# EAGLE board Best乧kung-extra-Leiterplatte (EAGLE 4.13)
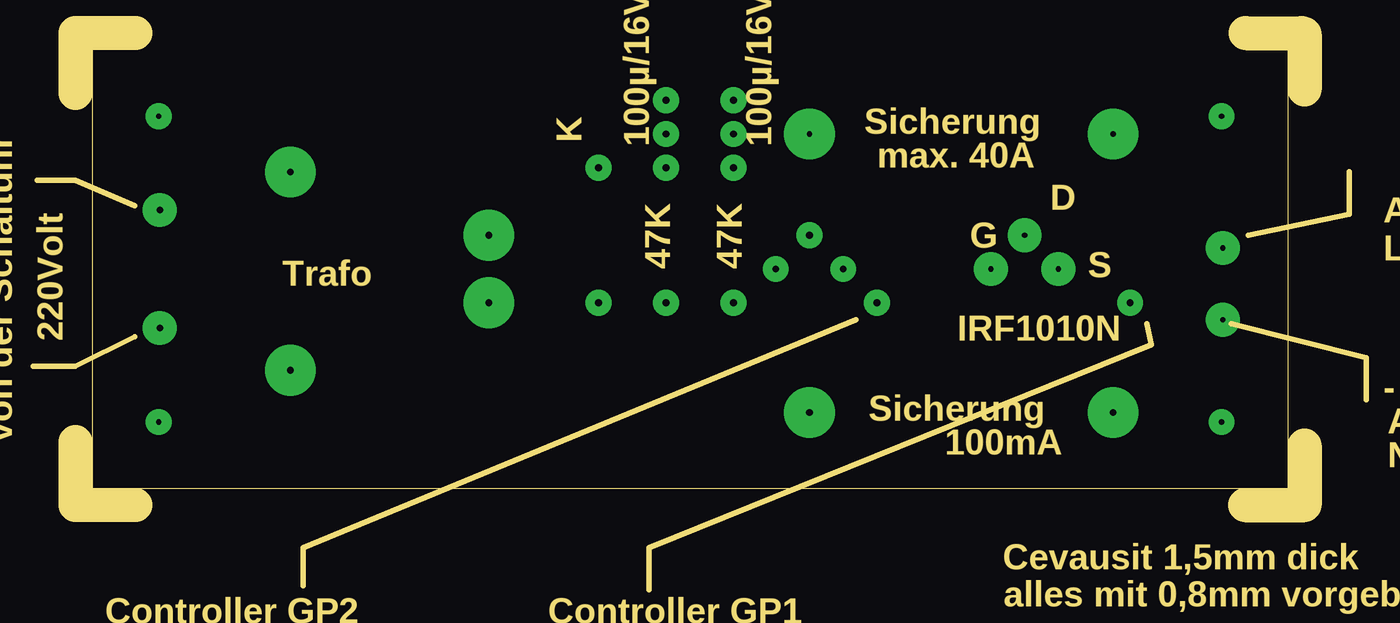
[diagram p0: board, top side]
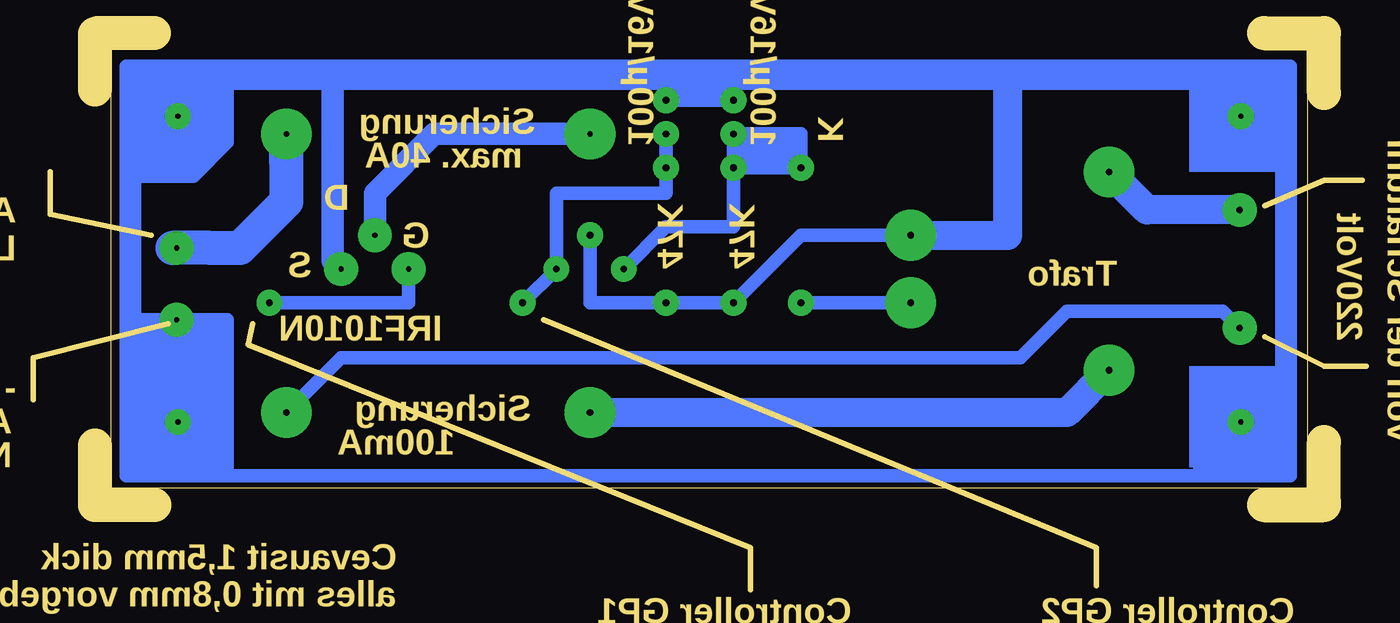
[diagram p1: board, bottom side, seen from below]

Size 100.33 x 41.87 mm. Coordinates in mm from the lower left corner, seen from the top.
Outline: 94.44,40.62 94.44,7.62 4.45,7.62 4.45,40.62
Outline: 3.2,37.37 3.2,41.87 7.7,41.87
Outline: 3.2,6.62 3.2,11.12
Outline: 7.7,6.37 3.2,6.37
Outline: 95.69,41.8 95.69,37.62
Outline: 95.69,10.87 95.69,6.37 91.19,6.37
Outline: 91.26,41.87 95.44,41.87
Outline: 91.44,26.67 99.06,28.26 99.06,31.43
Outline: 90.17,20 100.33,17.46 100.33,14.29
Outline: 61.91,20.32 20.32,3.17 20.32,0.32
Outline: 83.82,20 84.14,18.41 46.35,3.17 46.35,0
Outline: 7.62,28.89 3.18,30.8 0.32,30.8
Outline: 7.62,19.05 3.18,16.83 0,16.83
Copper layers (1*16): Top 0.035mm / dielectric 1.5mm / Bottom 0.035mm
Design rules "default": minimum track width 10mil, minimum drill 24mil, track to track 8mil, track to pad 8mil, pad to pad 8mil, via to via 8mil, smd to smd 8mil, copper to edge 40mil, drill to drill 8mil, minimum pad ring 10mil, minimum via ring 8mil, stop-mask expansion 4mil, vias tented up to drill 0mil, thermal gap 10mil

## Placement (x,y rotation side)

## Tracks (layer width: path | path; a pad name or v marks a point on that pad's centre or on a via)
S$1  (via drill 0.4 pad 1.93)
  other vias: 9.45,12.62
S$2  (via drill 0.4 pad 1.93)
  other vias: 9.45,35.62
S$3  (via drill 0.4 pad 1.93)
  other vias: 89.44,12.62
S$4  (via drill 0.4 pad 1.93)
  other vias: 89.44,35.62
S$5  (via drill 0.4 pad 2.54, 0.5 pad 1.93)
  Bottom 1.016: v72.07,24.13 72.07,21.59 v82.55,21.59
S$7  (via drill 0.5 pad 1.93, 0.5 pad 3.81)
  Bottom 1.016: v42.55,21.59 v34.29,21.59
S$8  (via drill 0.4 pad 2.54, 0.4 pad 3.81)
  Bottom 1.676: v58.42,34.29 70.17,34.29 74.61,29.85 v74.61,26.67
S$9  (via drill 0.5 pad 3.81)
  Bottom 2.184: 29.21,13.34 31.43,13.34 | 31.43,13.34 v58.42,13.34 | v19.37,16.51 22.54,13.34 31.43,13.34
S$10  (via drill 0.4 pad 2.54, 0.4 pad 3.81)
  Bottom 1.016: 81.28,29.21 81.28,32.07 | v89.53,25.72 87,25.72 84.77,25.72
  Bottom 2.54: 81.28,32.07 v81.28,34.29 81.28,29.21 84.77,25.72 87,25.72 89.85,25.72
S$15  (via drill 0.5 pad 2.54, 0.5 pad 3.81)
  Bottom 2.184: v9.53,28.57 16.51,28.57 v19.37,31.43
S$17  (via drill 0.5 pad 2.54, 0.5 pad 3.81)
  Bottom 1.016: v81.28,13.34 77.15,17.46 26.04,17.46 22.54,20.96 10.79,20.96 v9.53,19.68
S$21  (via drill 0.5 pad 1.93)
  Bottom 1.016: v47.62,31.75 v47.62,34.29 42.55,34.29 v42.55,31.75 v47.62,31.75 | v47.62,31.75 47.62,27.3 52.7,27.3 v55.88,24.13
S$22  (via drill 0.4 pad 2.54)
  Bottom 1.016: 92.71,30.48 92.71,20.32 v89.53,20.32 85.72,20.32 85.72,8.89
S$23  (via drill 0.5 pad 1.93, 0.5 pad 3.81)
  Bottom 1.016: v58.42,26.67 58.42,21.59 v52.7,21.59 v47.62,21.59 42.55,26.67 v34.29,26.67
  Bottom 2.184: v34.29,26.67 26.99,26.67 26.99,38.42
S$25  (via drill 0.5 pad 1.93)
  Bottom 1.016: 47.62,38.73 v47.62,36.83 v52.7,36.83 52.7,38.42
S$26  (via drill 0.5 pad 1.93)
  Bottom 1.016: v52.7,34.29 v52.7,31.75 52.7,29.85 60.96,29.85 v60.96,24.13 v63.5,21.59
S$28  (via drill 0.4 pad 2.54)
  Bottom 1.016: 93.03,31.12 88.26,31.12 85.72,33.66 85.72,38.1 | 85.72,38.1 85.72,38.73 | 80.33,38.1 81.28,38.1 | 80.33,38.1 85.72,38.1 | 12.38,38.1 77.79,38.1 80.33,38.1
  Bottom 1.676: v77.15,24.13 77.79,24.77 77.79,38.1
S$34
  Bottom 1.016: 6.35,39.37 6.35,15.88 | 93.34,8.89 93.34,39.37 6.35,39.37 | 6.35,39.37 5.71,39.37 5.71,9.53 | 5.71,9.53 5.71,9.21 | 5.71,9.53 5.71,8.57 17.46,8.57 | 17.46,8.57 93.34,8.57 | 17.46,8.57 16.19,8.57
S$42
  Bottom 1.016: 31.12,38.73 31.12,38.42
(copper drawn outside any net)
  shapes: Bottom area x13

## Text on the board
Vias: Auf Bestückungsseite gesehen ! | extra Leiterplatte
Dimension: K | Sicherung | K | 100µ/16V | 100µ/16V | max. 40A | D | Aquarium- | G | 47K | 47K | LED | S | IRF1010N | Trafo | 220Volt | IRF1010N | an | (3) | - | Sicherung | Aquarium- | von der Schaltuhr | 100mA | Netzteil | Cevausit 1,5mm dick | alles mit 0,8mm vorgebohrt | Controller GP2 | Controller GP1 | Aufbohren wie folgt: | G | S | (1) | (2) | D | an Controller Leiterplatte | IRF 1010N 1,0mm
tOrigins: 78L05 | 1N4002 | Katode | Anode | Ausg. | Eing. | Masse | 78L05 | Ausg. | 1N4002 | 4Stck. Befestigungsbohr... 3,2mm | Sicherungshalter 1,5mm | Anschluß-Drähte 1,0mm | 1N4002 1,0mm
